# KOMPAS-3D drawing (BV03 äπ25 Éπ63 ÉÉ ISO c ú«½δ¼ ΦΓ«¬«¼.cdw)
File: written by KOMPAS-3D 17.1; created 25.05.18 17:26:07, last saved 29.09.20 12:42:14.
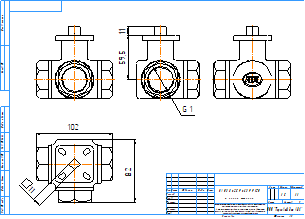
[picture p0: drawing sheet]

Sheet 1: A3, landscape

Title block, sheet 1: name: BV03 Ду25 Ру63 РР ISO / c голым штоком; material: Сталь 20  ГОСТ 1050-88; mass: 1,5; sheets: 1; sheet format: A3; stored path: C:\Users\kka\KOMPAS_Work\!Trash\BV3 кран трехходовой шаровой\KOMPAS 2D\BV03 Ду25 Ру63 РР ISO c голым штоком.cdw

Views: Вид 1, Проекционный вид 2, Проекционный вид 3, Проекционный вид 4
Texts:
  kka
  adl
  Рама для чертежей
  Лит-Масса-Масштаб
  Материал-Предприятие
  Масштаб
  Изм.
  Лист
  № докум.
  Подп.
  Дата
  Лит.
  Разраб.
  Пров.
  Т.контр.
  Листов
  Внимание! Данный продукт является объектом авторского права ООО «Торговый Дом АДЛ».
  Запрещается изменение, копирование, распространение
  (в том числе путем копирования на другие сайты и ресурсы в Интернете)
  или любое иное использование информации и объектов без предварительного
  согласия правообладателя (ООО «Торговый Дом АДЛ»).
  Н.контр.
  Утв.
  ООО "Торговый дом АДЛ"
  Изменение
  Номер документа
  Подпись
  Обозначение документа
  Наименование изделия
  Масса изделия по ГОСТ 2.109-73
  Порядковый номер листа
  Общее количество листов в документе
  Характер работы, выполненной лицом, подписавшим документ
  Наименование или индекс предприятия, выпускающего документ
  Инв. № подл.
  Подп. и дата
  Взам. инв. №
  Инв. № дубл.
  Инвентарный номер подлинника по ГОСТ 2.501-68
  Подпись принявшего подлинник в отдел технической документации
  Инвентарный номер подлинника, взамен которого выпущен данный подлинник
  Инвентарный номер дубликата по ГОСТ 2.502-68
  Подпись принявшего дубликат в отдел технической документации
  Справ. №
  Перв. примен.
  Обозначение документа, взамен или на основании которого выпущен данный документ
  Обозначение документа, в котором впервые записан данный документ
  Подпись лица, копировавшего чертеж
  Обозначение формата листа
  !Рама для чертежа
Dimensions and other numbers on the sheet: 1; 59,5; 11; 82; 102; 1:1; 1,5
